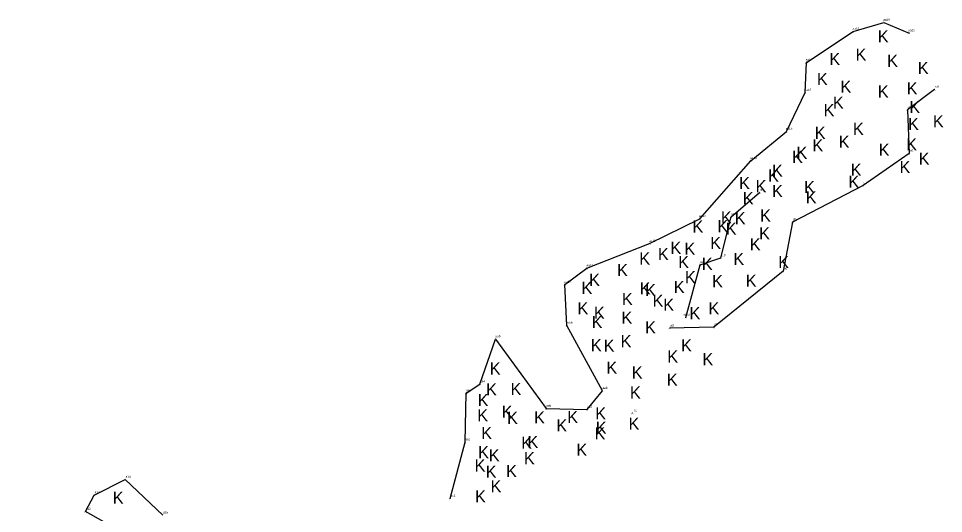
# Model space of a CAD drawing. Extents: x 2028512 to 2029541, y 737100 to 738747.
# Drawn here: x 2028891 to 2029541, y 738399 to 738747 of the extents above; entities that cross this region are included whole.
import ezdxf

# ---------------------------------------------------------------- set-up
doc = ezdxf.new("R2010")
doc.units = 0
for name, color, linetype in [('Old_Level_10', 7, 'Continuous'), ('Old_Level_20', 7, 'Continuous'), ('Old_Level_52', 7, 'Continuous'), ('Old_Level_61', 7, 'Continuous')]:
    doc.layers.add(name, color=color, linetype=linetype)

msp = doc.modelspace()

# ---------------------------------------------------------------- linework, layer by layer
at = {"layer": 'Old_Level_10'}
for points in [[(2029534.39, 738696.87), (2029515.31, 738682.56), (2029516.49, 738651.91), (2029484.26, 738629.37), (2029434.66, 738603.73), (2029427.91, 738569.15), (2029379.37, 738529.91), (2029348.23, 738529.08)], [(2029384.32, 738578.52), (2029391.54, 738607.5), (2029411.43, 738624.51)], [(2029359.54, 738536.62), (2029369.65, 738573.79), (2029384.32, 738578.52)]]:
    msp.add_lwpolyline(points, dxfattribs=at)
at = {"layer": 'Old_Level_52'}
for points in [[(2029193.85, 738409.54), (2029204.51, 738449.08), (2029205.22, 738483.49), (2029214.88, 738489.83), (2029225.8, 738521.55), (2029261.44, 738472.75), (2029290.23, 738471.91), (2029301.03, 738485.2), (2029275.97, 738531.04), (2029274.51, 738559.77), (2029290.05, 738571.33), (2029334.12, 738588.59), (2029369.39, 738606.07), (2029405.21, 738646.75), (2029430.3, 738667.41), (2029443.59, 738694.72), (2029444.31, 738715.95), (2029477.29, 738737.64), (2029498.82, 738744.06), (2029516.54, 738736.6)], [(2028904.65, 738196.15), (2028890.57, 738227.25), (2028922.11, 738225.85), (2028932.53, 738230.73), (2028946.73, 738259.58), (2028951.13, 738263.7), (2028950.51, 738268.13), (2028918.78, 738305.31), (2028920.65, 738342.72), (2028937.45, 738359.38), (2028945.21, 738340.29), (2028965.8, 738354.45), (2028965.12, 738369.93), (2028963.42, 738385.89), (2028937.56, 738400.24), (2028943.82, 738411.81), (2028965.6, 738422.83), (2028991.98, 738397.81)]]:
    msp.add_lwpolyline(points, dxfattribs=at)

# ---------------------------------------------------------------- texts
at = {"layer": 'Old_Level_10'}
for p in [(2029494.52, 738730.04), (2029460.47, 738714.11), (2029478.9, 738717.23), (2029501.08, 738712.86), (2029522.63, 738707.86), (2029451.73, 738700.04), (2029468.28, 738694.73), (2029514.82, 738693.48), (2029494.52, 738691.29), (2029462.97, 738683.48), (2029516.7, 738680.35), (2029456.41, 738678.17), (2029515.76, 738668.48), (2029533.25, 738670.35), (2029450.16, 738662.23), (2029477.03, 738665.04), (2029467.03, 738655.98), (2029437.36, 738648.17), (2029448.6, 738653.48), (2029495.14, 738650.35), (2029514.51, 738654.1), (2029434.24, 738645.35), (2029523.26, 738644.1), (2029420.18, 738635.66), (2029475.47, 738636.29), (2029509.82, 738638.17), (2029417.37, 738632.23), (2029397.07, 738626.91), (2029408.62, 738624.73), (2029442.67, 738624.1), (2029473.9, 738627.85), (2029399.56, 738616.29), (2029420.18, 738621.29), (2029443.92, 738616.91), (2029384.26, 738602.85), (2029393.94, 738602.23), (2029411.75, 738604.1), (2029364.27, 738596.41), (2029381.76, 738596.6), (2029387.69, 738594.85), (2029411.12, 738591.6), (2029376.76, 738584.85), (2029404.56, 738583.91), (2029340, 738577.04), (2029348.74, 738581.41), (2029358.65, 738580.79), (2029326.88, 738573.91), (2029354.27, 738571.41), (2029370.83, 738570.16), (2029393, 738573.6), (2029424.55, 738571.41), (2029311.26, 738565.79), (2029291.58, 738558.91), (2029358.96, 738560.79), (2029378.01, 738557.97), (2029401.75, 738558.29), (2029286.27, 738553.29), (2029327.19, 738552.97), (2029330.94, 738551.72), (2029351.15, 738553.91), (2029314.7, 738545.47), (2029336.25, 738544.22), (2029283.46, 738538.91), (2029343.75, 738541.41), (2029375.51, 738538.91), (2029295.02, 738535.79), (2029314.39, 738532.35), (2029362.18, 738535.47), (2029293.46, 738529.22), (2029330.94, 738525.47), (2029292.83, 738512.97), (2029301.89, 738512.66), (2029313.76, 738515.78), (2029356.24, 738512.82), (2029346.56, 738505), (2029371.23, 738503.13), (2029221.74, 738496.57), (2029303.77, 738497.19), (2029321.57, 738493.75), (2029346.25, 738488.75), (2029219.24, 738481.88), (2029236.42, 738482.19), (2029320.32, 738479.69), (2029213.31, 738474.38), (2029230.17, 738466.25), (2029213, 738463.75), (2029233.92, 738461.88), (2029252.98, 738462.19), (2029276.28, 738462.5), (2029295.96, 738465), (2029268.59, 738456.56), (2029296.27, 738455), (2029319.38, 738457.81), (2029215.81, 738451.25), (2029295.46, 738451.03), (2029243.92, 738444.38), (2029248.29, 738445), (2029213.62, 738437.81), (2029221.12, 738435.63), (2029245.79, 738433.53), (2029282.65, 738439.47), (2029211.12, 738428.44), (2029218.93, 738424.06), (2029233.3, 738424.47), (2029222.37, 738413.84), (2028956.85, 738405.84), (2029211.43, 738406.66)]:
    msp.add_text('K', height=8.5, dxfattribs=at).set_placement(p)
at = {"layer": 'Old_Level_20'}
for p in [(2029498.07, 738743.31), (2029476.54, 738736.89), (2029515.79, 738735.85), (2029443.56, 738715.2), (2029442.84, 738693.97), (2029533.64, 738696.12), (2029514.56, 738681.81), (2029429.55, 738666.66), (2029515.74, 738651.16), (2029404.46, 738646), (2029410.68, 738623.76), (2029483.51, 738628.62), (2029368.64, 738605.32), (2029390.79, 738606.75), (2029433.91, 738602.98), (2029333.37, 738587.84), (2029383.57, 738577.77), (2029289.3, 738570.58), (2029368.9, 738573.04), (2029427.16, 738568.4), (2029273.76, 738559.02), (2029358.79, 738535.87), (2029275.22, 738530.29), (2029347.48, 738528.33), (2029378.62, 738529.16), (2029225.05, 738520.8), (2029214.13, 738489.08), (2029204.47, 738482.74), (2029300.28, 738484.45), (2029260.69, 738472), (2029289.48, 738471.16), (2029321.31, 738468.73), (2029321.31, 738468.73), (2029321.31, 738468.73), (2029321.31, 738468.73), (2029203.76, 738448.33), (2028964.85, 738422.08), (2028964.85, 738422.08), (2028964.85, 738422.08), (2028964.85, 738422.08), (2028943.07, 738411.06), (2028943.07, 738411.06), (2028943.07, 738411.06), (2028943.07, 738411.06), (2029193.1, 738408.79), (2028936.81, 738399.49), (2028936.81, 738399.49), (2028936.81, 738399.49), (2028936.81, 738399.49)]:
    msp.add_text('A', height=1.5, dxfattribs=at).set_placement(p)
at = {"layer": 'Old_Level_61'}
for s, p in [('aa19', (2029498.38, 738745.31)), ('aa18', (2029476.85, 738738.89)), ('aa20', (2029515.85, 738737.85)), ('aa17', (2029443.87, 738717.2)), ('aa16', (2029443.15, 738695.97)), ('st1', (2029534.88, 738698.12)), ('st2', (2029515.54, 738683.81)), ('aa15', (2029429.86, 738668.66)), ('st3', (2029516.72, 738653.16)), ('aa14', (2029404.77, 738648)), ('st4', (2029484.49, 738630.62)), ('ut5', (2029411.66, 738625.76)), ('aa13', (2029368.95, 738607.32)), ('ut4', (2029391.77, 738608.75)), ('st5', (2029434.9, 738604.98)), ('aa12', (2029333.69, 738589.84)), ('ut3', (2029384.55, 738579.77)), ('aa11', (2029289.87, 738572.58)), ('ut2', (2029369.89, 738575.04)), ('st6', (2029428.14, 738570.4)), ('aa10', (2029274.07, 738561.02)), ('st7ut1', (2029358.02, 738537.87)), ('AA9', (2029276.02, 738532.29)), ('st8', (2029348.47, 738530.33)), ('st7', (2029379.61, 738531.16)), ('aa5', (2029225.84, 738522.8)), ('aa4', (2029214.93, 738491.08)), ('aa8', (2029301.07, 738486.45)), ('aa3', (2029205.27, 738484.74)), ('aa6', (2029261.48, 738474)), ('aa7', (2029290.27, 738473.16)), ('s1', (2029323.19, 738470.73)), ('s1', (2029323.19, 738470.73)), ('s1', (2029323.19, 738470.73)), ('s1', (2029323.19, 738470.73)), ('aa2', (2029204.56, 738450.33)), ('a14', (2028965.9, 738424.08)), ('a14', (2028965.9, 738424.08)), ('a14', (2028965.9, 738424.08)), ('a14', (2028965.9, 738424.08)), ('a13', (2028944.11, 738413.06)), ('a13', (2028944.11, 738413.06)), ('a13', (2028944.11, 738413.06)), ('a13', (2028944.11, 738413.06)), ('aa1', (2029194.15, 738410.79)), ('a12', (2028937.86, 738401.49)), ('a12', (2028937.86, 738401.49)), ('a12', (2028937.86, 738401.49)), ('a12', (2028937.86, 738401.49)), ('a15', (2028992.28, 738399.06)), ('a15', (2028992.28, 738399.06)), ('a15', (2028992.28, 738399.06)), ('a15', (2028992.28, 738399.06))]:
    msp.add_text(s, height=1.5, dxfattribs=at).set_placement(p)

doc.saveas('drawing.dxf')
